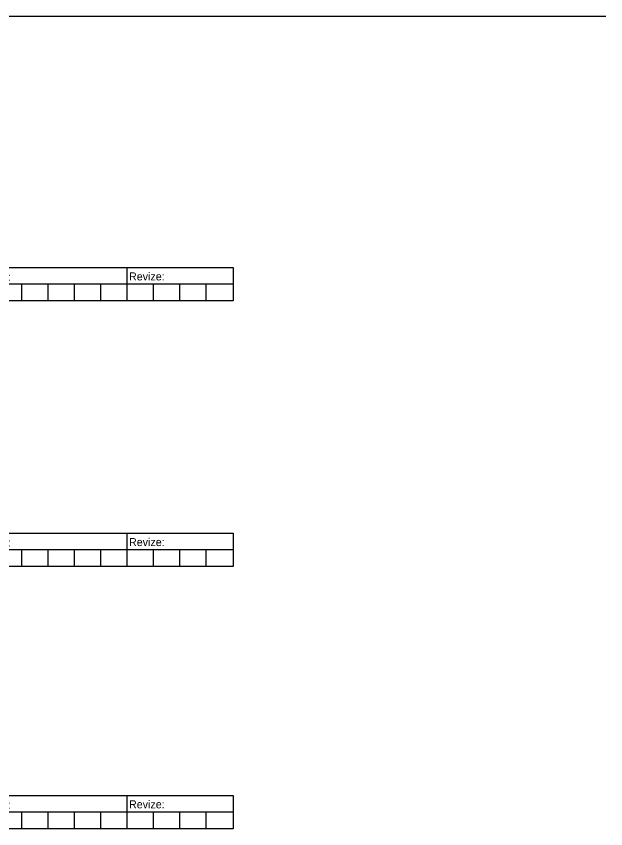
# Model space of a CAD drawing. Extents: x 1391 to 5528, y -6194 to 565.
# Drawn here: x 4555 to 5439, y -2428 to -1211 of the extents above; entities that cross this region are included whole.
import ezdxf

# ---------------------------------------------------------------- set-up
doc = ezdxf.new("R2010")
doc.units = 0
doc.layers.add('Vrstva 11', color=7, linetype='Continuous')
doc.layers.add('Vrstva 8', color=7, linetype='Continuous')

# ---------------------------------------------------------------- blocks, each defined once
blk = doc.blocks.new('_U1')
at = {"layer": 'Vrstva 8'}
for p, q in [((-4.55, 0.25), (-4.55, -0.25)), ((-2.575, 0.25), (-2.575, -0.25)), ((-0.205, 0.25), (-0.205, -0.25)), ((3.35, 0.25), (3.35, -0.25)), ((4.535, 0.25), (4.535, -0.25)), ((6.905, 0.25), (6.905, -0.25)), ((8.5, 0), (-8.5, 0)), ((-8.105, 0), (-8.105, -0.25)), ((-7.71, 0), (-7.71, -0.25)), ((-7.315, 0), (-7.315, -0.25)), ((-6.92, 0), (-6.92, -0.25)), ((-6.525, 0), (-6.525, -0.25)), ((-6.13, 0), (-6.13, -0.25)), ((-5.735, 0), (-5.735, -0.25)), ((-5.34, 0), (-5.34, -0.25)), ((-4.945, 0), (-4.945, -0.25)), ((-4.155, 0), (-4.155, -0.25)), ((-3.76, 0), (-3.76, -0.25)), ((-3.365, 0), (-3.365, -0.25)), ((-2.97, 0), (-2.97, -0.25)), ((-2.18, 0), (-2.18, -0.25)), ((-1.785, 0), (-1.785, -0.25)), ((-1.39, 0), (-1.39, -0.25)), ((-0.995, 0), (-0.995, -0.25)), ((-0.6, 0), (-0.6, -0.25)), ((0.19, 0), (0.19, -0.25)), ((0.585, 0), (0.585, -0.25)), ((0.98, 0), (0.98, -0.25)), ((1.375, 0), (1.375, -0.25)), ((1.77, 0), (1.77, -0.25)), ((2.165, 0), (2.165, -0.25)), ((2.56, 0), (2.56, -0.25)), ((2.955, 0), (2.955, -0.25)), ((3.745, 0), (3.745, -0.25)), ((4.14, 0), (4.14, -0.25)), ((4.93, 0), (4.93, -0.25)), ((5.325, 0), (5.325, -0.25)), ((5.72, 0), (5.72, -0.25)), ((6.115, 0), (6.115, -0.25)), ((6.51, 0), (6.51, -0.25)), ((7.3, 0), (7.3, -0.25)), ((7.695, 0), (7.695, -0.25)), ((8.09, 0), (8.09, -0.25))]:
    blk.add_line(p, q, dxfattribs=at)
blk.add_lwpolyline([(-8.5, 0.25), (8.5, 0.25), (8.5, -0.25), (-8.5, -0.25)], close=True, dxfattribs=at)
for s, p in [('S-kód:', (-8.445, 0.049)), ('Stupeň dokumentace:', (-4.497, 0.065)), ('Část:', (-2.534, 0.034)), ('Objekt:', (-0.157, 0.07)), ('Podobjekt:', (3.364, 0.07)), ('Příloha:', (4.607, 0.049)), ('Revize:', (6.936, 0.056))]:
    blk.add_text(s, height=0.12, dxfattribs=at).set_placement(p)

msp = doc.modelspace()

# ---------------------------------------------------------------- linework, layer by layer
at = {"layer": 'Vrstva 11'}
msp.add_line((1390.7, -1210.7), (5439, -1210.7), dxfattribs=at)

# ---------------------------------------------------------------- block references
at = {"layer": 'Vrstva 8', "xscale": 100, "yscale": 100}
for p in [(4030.6, -1612.2), (4030.6, -2010.3), (4030.6, -2403.3)]:
    msp.add_blockref('_U1', p, dxfattribs=at)

doc.saveas('drawing.dxf')
